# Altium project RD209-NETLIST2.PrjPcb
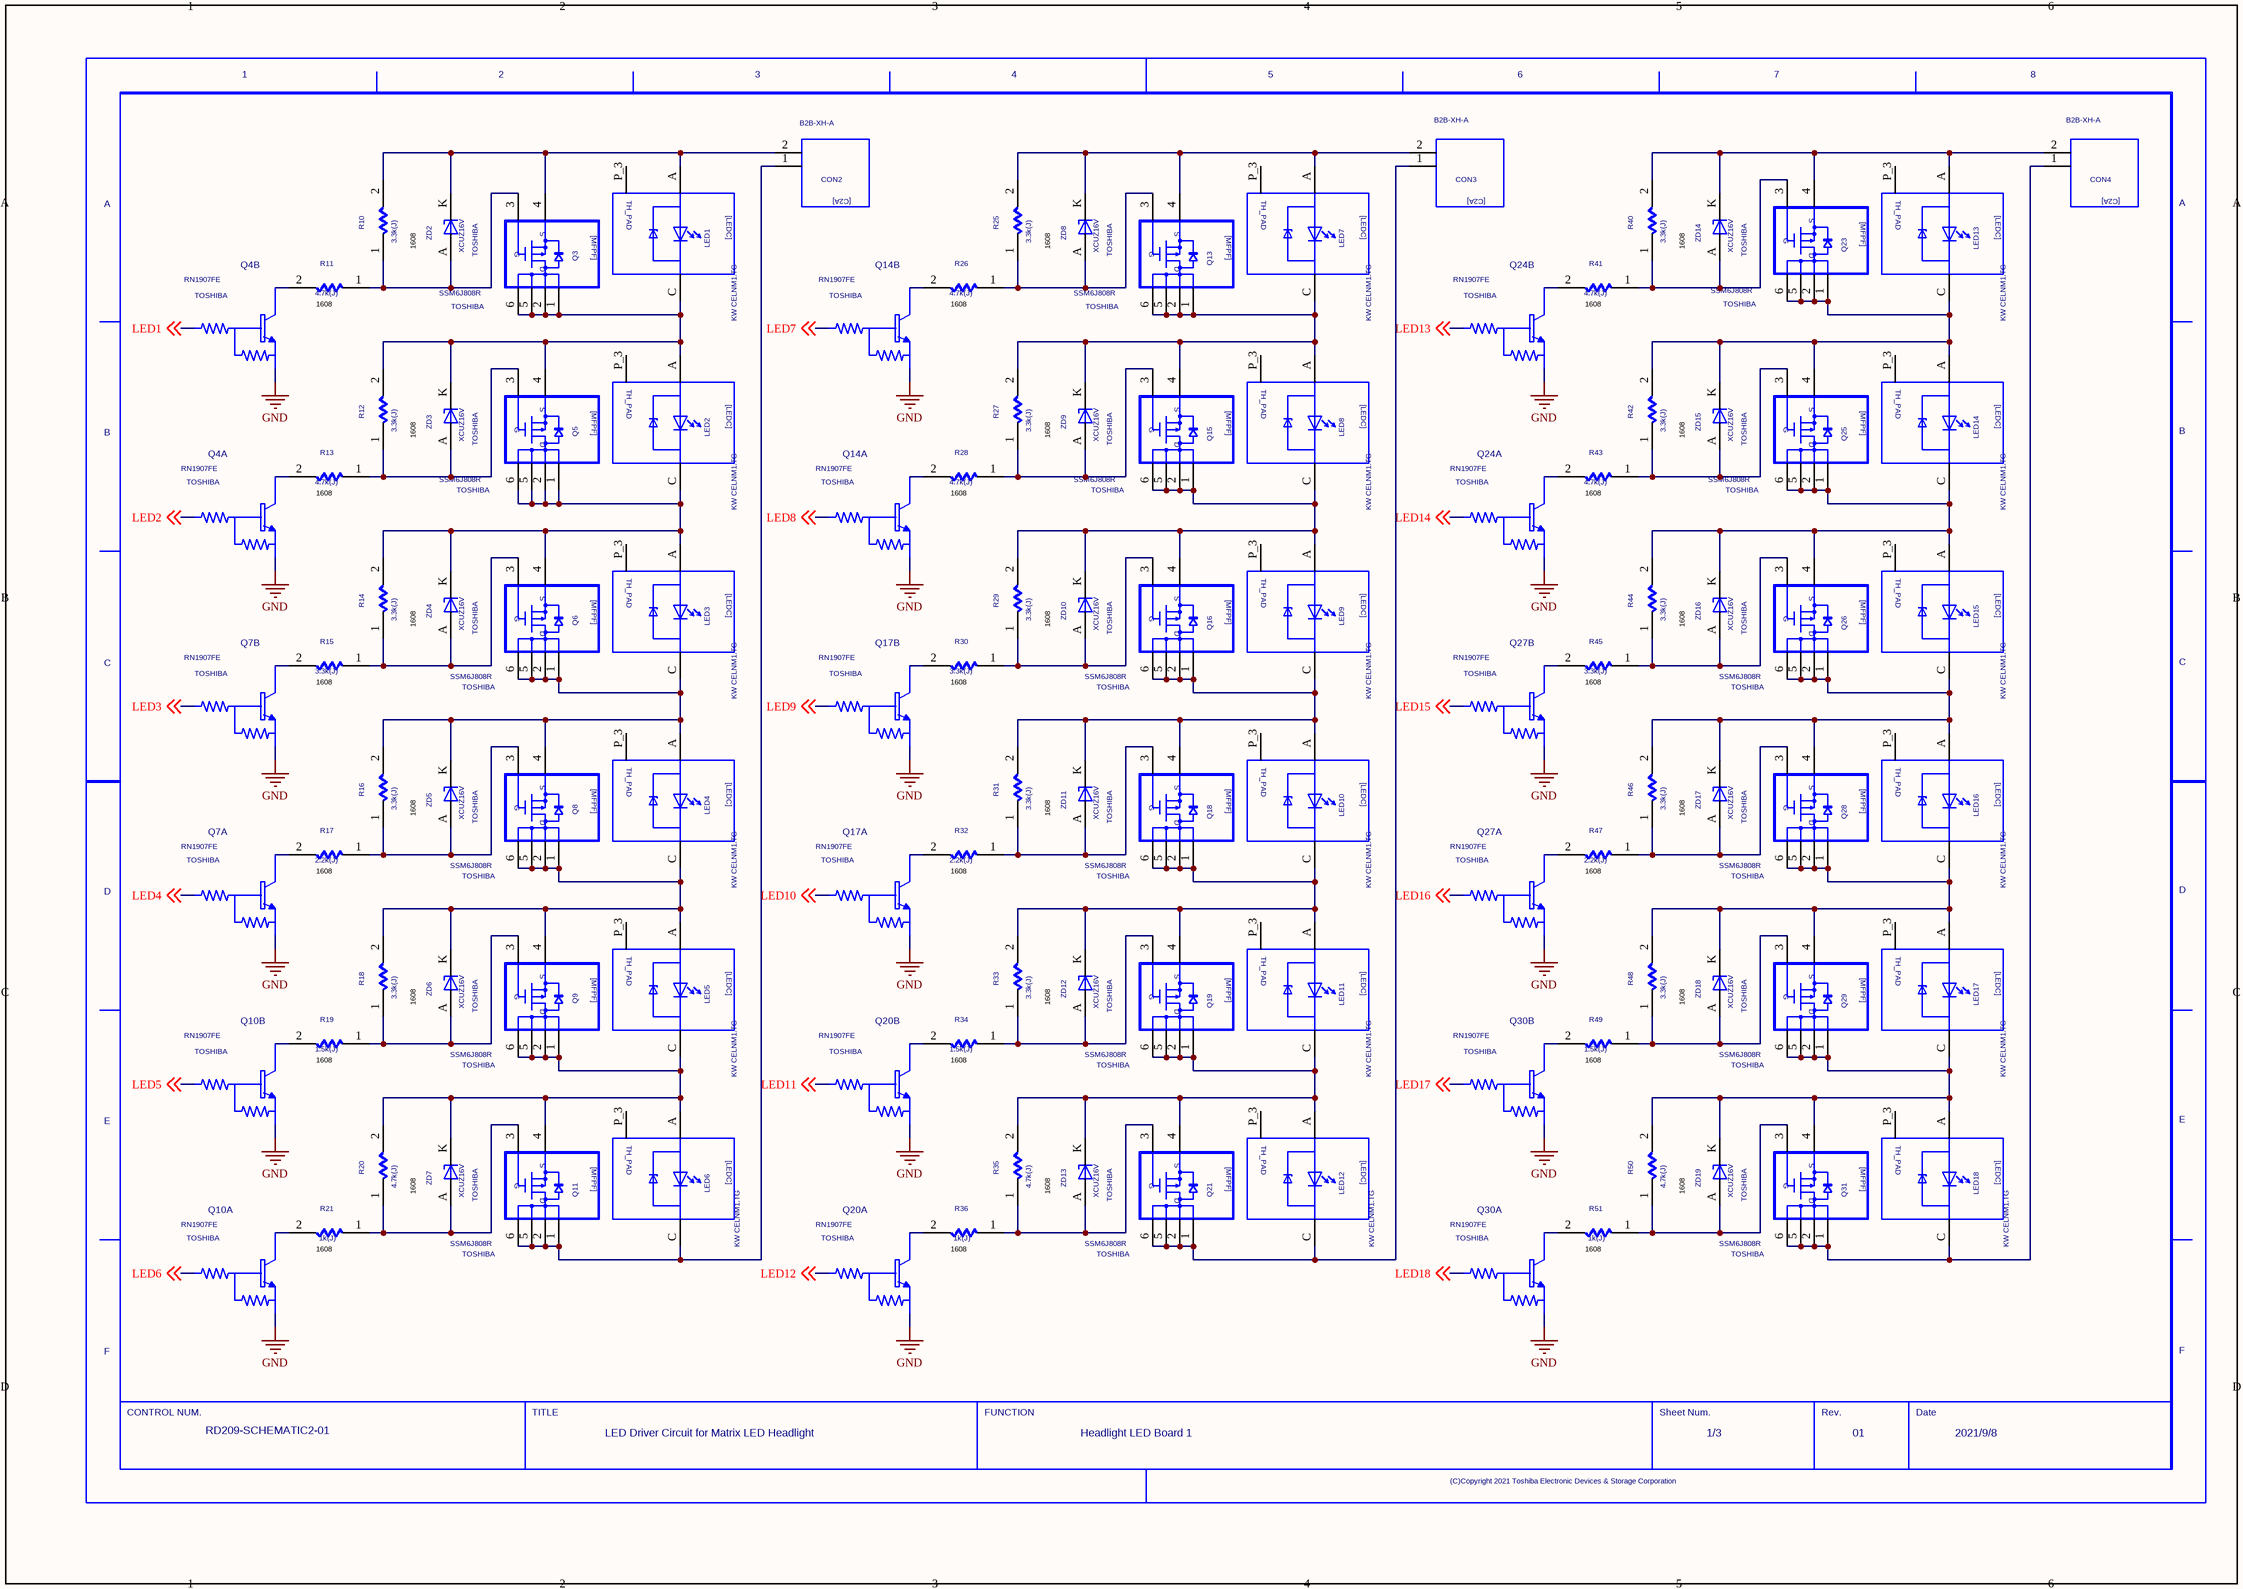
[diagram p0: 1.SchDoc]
3 sheets, 243 parts. Net scope: global (net labels, ports and power ports of the same name join across sheets).
Sheets:
  1.SchDoc
  2.SchDoc
  3.SchDoc

## Sheet 1.SchDoc
size 420 x 297 mm

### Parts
(Parts that share a designator on the sheet are numbered #1, #2 ... from top to bottom, then left to right.)
CON2  VAL3: B2B-XH-A  (hidden comment: C2A)
CON3  VAL3: B2B-XH-A  (hidden comment: C2A)
CON4  VAL3: B2B-XH-A  (hidden comment: C2A)
LED1  VAL3: KW CELNM1.TG  (hidden comment: LEDC)
LED2  VAL3: KW CELNM1.TG  (hidden comment: LEDC)
LED3  VAL3: KW CELNM1.TG  (hidden comment: LEDC)
LED4  VAL3: KW CELNM1.TG  (hidden comment: LEDC)
LED5  VAL3: KW CELNM1.TG  (hidden comment: LEDC)
LED6  VAL3: KW CELNM1.TG  (hidden comment: LEDC)
LED7  VAL3: KW CELNM1.TG  (hidden comment: LEDC)
LED8  VAL3: KW CELNM1.TG  (hidden comment: LEDC)
LED9  VAL3: KW CELNM1.TG  (hidden comment: LEDC)
LED10  VAL3: KW CELNM1.TG  (hidden comment: LEDC)
LED11  VAL3: KW CELNM1.TG  (hidden comment: LEDC)
LED12  VAL3: KW CELNM1.TG  (hidden comment: LEDC)
LED13  VAL3: KW CELNM1.TG  (hidden comment: LEDC)
LED14  VAL3: KW CELNM1.TG  (hidden comment: LEDC)
LED15  VAL3: KW CELNM1.TG  (hidden comment: LEDC)
LED16  VAL3: KW CELNM1.TG  (hidden comment: LEDC)
LED17  VAL3: KW CELNM1.TG  (hidden comment: LEDC)
LED18  VAL3: KW CELNM1.TG  (hidden comment: LEDC)
Q3  USERCOMPTEXT3: TOSHIBA  VAL3: SSM6J808R  (hidden comment: MFPF)
Q4  USERCOMPTEXT3: TOSHIBA  VAL3: RN1907FE  (hidden comment: RN1907FE_1)  (parts A,B of 2)
Q5  USERCOMPTEXT3: TOSHIBA  VAL3: SSM6J808R  (hidden comment: MFPF)
Q6  USERCOMPTEXT3: TOSHIBA  VAL3: SSM6J808R  (hidden comment: MFPF)
Q7  USERCOMPTEXT3: TOSHIBA  VAL3: RN1907FE  (hidden comment: RN1907FE_1)  (parts A,B of 2)
Q8  USERCOMPTEXT3: TOSHIBA  VAL3: SSM6J808R  (hidden comment: MFPF)
Q9  USERCOMPTEXT3: TOSHIBA  VAL3: SSM6J808R  (hidden comment: MFPF)
Q10  USERCOMPTEXT3: TOSHIBA  VAL3: RN1907FE  (hidden comment: RN1907FE_1)  (parts A,B of 2)
Q11  USERCOMPTEXT3: TOSHIBA  VAL3: SSM6J808R  (hidden comment: MFPF)
Q13  USERCOMPTEXT3: TOSHIBA  VAL3: SSM6J808R  (hidden comment: MFPF)
Q14  USERCOMPTEXT3: TOSHIBA  VAL3: RN1907FE  (hidden comment: RN1907FE_1)  (parts A,B of 2)
Q15  USERCOMPTEXT3: TOSHIBA  VAL3: SSM6J808R  (hidden comment: MFPF)
Q16  USERCOMPTEXT3: TOSHIBA  VAL3: SSM6J808R  (hidden comment: MFPF)
Q17  USERCOMPTEXT3: TOSHIBA  VAL3: RN1907FE  (hidden comment: RN1907FE_1)  (parts A,B of 2)
Q18  USERCOMPTEXT3: TOSHIBA  VAL3: SSM6J808R  (hidden comment: MFPF)
Q19  USERCOMPTEXT3: TOSHIBA  VAL3: SSM6J808R  (hidden comment: MFPF)
Q20  USERCOMPTEXT3: TOSHIBA  VAL3: RN1907FE  (hidden comment: RN1907FE_1)  (parts A,B of 2)
Q21  USERCOMPTEXT3: TOSHIBA  VAL3: SSM6J808R  (hidden comment: MFPF)
Q23  USERCOMPTEXT3: TOSHIBA  VAL3: SSM6J808R  (hidden comment: MFPF)
Q24  USERCOMPTEXT3: TOSHIBA  VAL3: RN1907FE  (hidden comment: RN1907FE_1)  (parts A,B of 2)
Q25  USERCOMPTEXT3: TOSHIBA  VAL3: SSM6J808R  (hidden comment: MFPF)
Q26  USERCOMPTEXT3: TOSHIBA  VAL3: SSM6J808R  (hidden comment: MFPF)
Q27  USERCOMPTEXT3: TOSHIBA  VAL3: RN1907FE  (hidden comment: RN1907FE_1)  (parts A,B of 2)
Q28  USERCOMPTEXT3: TOSHIBA  VAL3: SSM6J808R  (hidden comment: MFPF)
Q29  USERCOMPTEXT3: TOSHIBA  VAL3: SSM6J808R  (hidden comment: MFPF)
Q30  USERCOMPTEXT3: TOSHIBA  VAL3: RN1907FE  (hidden comment: RN1907FE_1)  (parts A,B of 2)
Q31  USERCOMPTEXT3: TOSHIBA  VAL3: SSM6J808R  (hidden comment: MFPF)
R10  VAL1: 3.3k(J)  (hidden comment: R)
R11  VAL1: 4.7k(J)  (hidden comment: R)
R12  VAL1: 3.3k(J)  (hidden comment: R)
R13  VAL1: 4.7k(J)  (hidden comment: R)
R14  VAL1: 3.3k(J)  (hidden comment: R)
R15  VAL1: 3.3k(J)  (hidden comment: R)
R16  VAL1: 3.3k(J)  (hidden comment: R)
R17  VAL1: 2.2k(J)  (hidden comment: R)
R18  VAL1: 3.3k(J)  (hidden comment: R)
R19  VAL1: 1.5k(J)  (hidden comment: R)
R20  VAL1: 4.7k(J)  (hidden comment: R)
R21  VAL1: 1k(J)  (hidden comment: R)
R25  VAL1: 3.3k(J)  (hidden comment: R)
R26  VAL1: 4.7k(J)  (hidden comment: R)
R27  VAL1: 3.3k(J)  (hidden comment: R)
R28  VAL1: 4.7k(J)  (hidden comment: R)
R29  VAL1: 3.3k(J)  (hidden comment: R)
R30  VAL1: 3.3k(J)  (hidden comment: R)
R31  VAL1: 3.3k(J)  (hidden comment: R)
R32  VAL1: 2.2k(J)  (hidden comment: R)
R33  VAL1: 3.3k(J)  (hidden comment: R)
R34  VAL1: 1.5k(J)  (hidden comment: R)
R35  VAL1: 4.7k(J)  (hidden comment: R)
R36  VAL1: 1k(J)  (hidden comment: R)
R40  VAL1: 3.3k(J)  (hidden comment: R)
R41  VAL1: 4.7k(J)  (hidden comment: R)
R42  VAL1: 3.3k(J)  (hidden comment: R)
R43  VAL1: 4.7k(J)  (hidden comment: R)
R44  VAL1: 3.3k(J)  (hidden comment: R)
R45  VAL1: 3.3k(J)  (hidden comment: R)
R46  VAL1: 3.3k(J)  (hidden comment: R)
R47  VAL1: 2.2k(J)  (hidden comment: R)
R48  VAL1: 3.3k(J)  (hidden comment: R)
R49  VAL1: 1.5k(J)  (hidden comment: R)
R50  VAL1: 4.7k(J)  (hidden comment: R)
R51  VAL1: 1k(J)  (hidden comment: R)
U?#1  DATE: 2021/9/8  REVISION: 01  SHEETNUMBER: 1/3  FUNCTION: Headlight LED Board 1  TITLE: LED Driver Circuit for / Matrix LED Headlight  DRAWINGNUMBER: RD209-SCHEMATIC2-01  (hidden comment: WAKU_DEF100)
ZD2  USERCOMPTEXT3: TOSHIBA  VAL3: XCUZ16V  (hidden comment: ZD)
ZD3  USERCOMPTEXT3: TOSHIBA  VAL3: XCUZ16V  (hidden comment: ZD)
ZD4  USERCOMPTEXT3: TOSHIBA  VAL3: XCUZ16V  (hidden comment: ZD)
ZD5  USERCOMPTEXT3: TOSHIBA  VAL3: XCUZ16V  (hidden comment: ZD)
ZD6  USERCOMPTEXT3: TOSHIBA  VAL3: XCUZ16V  (hidden comment: ZD)
ZD7  USERCOMPTEXT3: TOSHIBA  VAL3: XCUZ16V  (hidden comment: ZD)
ZD8  USERCOMPTEXT3: TOSHIBA  VAL3: XCUZ16V  (hidden comment: ZD)
ZD9  USERCOMPTEXT3: TOSHIBA  VAL3: XCUZ16V  (hidden comment: ZD)
ZD10  USERCOMPTEXT3: TOSHIBA  VAL3: XCUZ16V  (hidden comment: ZD)
ZD11  USERCOMPTEXT3: TOSHIBA  VAL3: XCUZ16V  (hidden comment: ZD)
ZD12  USERCOMPTEXT3: TOSHIBA  VAL3: XCUZ16V  (hidden comment: ZD)
ZD13  USERCOMPTEXT3: TOSHIBA  VAL3: XCUZ16V  (hidden comment: ZD)
ZD14  USERCOMPTEXT3: TOSHIBA  VAL3: XCUZ16V  (hidden comment: ZD)
ZD15  USERCOMPTEXT3: TOSHIBA  VAL3: XCUZ16V  (hidden comment: ZD)
ZD16  USERCOMPTEXT3: TOSHIBA  VAL3: XCUZ16V  (hidden comment: ZD)
ZD17  USERCOMPTEXT3: TOSHIBA  VAL3: XCUZ16V  (hidden comment: ZD)
ZD18  USERCOMPTEXT3: TOSHIBA  VAL3: XCUZ16V  (hidden comment: ZD)
ZD19  USERCOMPTEXT3: TOSHIBA  VAL3: XCUZ16V  (hidden comment: ZD)

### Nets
GND: Q4.1 Q4.4 Q7.1 Q7.4 Q10.1 Q10.4 Q14.1 Q14.4 Q17.1 Q17.4 Q20.1 Q20.4 Q24.1 Q24.4 Q27.1 Q27.4 Q30.1 Q30.4  [also labelled SIG12, SIG18, SIG21, SIG26, SIG30, SIG34, SIG35, SIG40, SIG45, SIG51, SIG54, SIG59, SIG60, SIG66, SIG72, SIG74, SIG8]  [project net SIG101]
LED2: Q4.2 ; off-sheet LED2
LED3: Q7.5 ; off-sheet LED3
LED4: Q7.2 ; off-sheet LED4
LED5: Q10.5 ; off-sheet LED5
LED6: Q10.2 ; off-sheet LED6
LED7: Q14.5 ; off-sheet LED7
LED8: Q14.2 ; off-sheet LED8
LED9: Q17.5 ; off-sheet LED9
LED10: Q17.2 ; off-sheet LED10
LED11: Q20.5 ; off-sheet LED11
LED12: Q20.2 ; off-sheet LED12
LED13: Q24.5 ; off-sheet LED13
LED14: Q24.2 ; off-sheet LED14
LED15: Q27.5 ; off-sheet LED15
LED16: Q27.2 ; off-sheet LED16
LED17: Q30.5 ; off-sheet LED17
LED18: Q30.2 ; off-sheet LED18
LED+1: CON2.2 LED1.A Q3.4 R10.2 ZD2.K(C)
LED+2: CON3.2 LED7.A Q13.4 R25.2 ZD8.K(C)
LED+3: CON4.2 LED13.A Q23.4 R40.2 ZD14.K(C)
LED-1: CON2.1 LED6.C Q11.1 Q11.2 Q11.5 Q11.6
LED-2: CON3.1 LED12.C Q21.1 Q21.2 Q21.5 Q21.6
SIG1: Q4.5 ; off-sheet LED1  [also labelled LED1]
SIG2: Q4.3 R11.2
SIG3: Q3.3 R10.1 R11.1 ZD2.A
SIG6: Q5.3 R12.1 R13.1 ZD3.A
SIG7: Q4.6 R13.2
SIG10: Q7.6 R17.2
SIG11: Q8.3 R16.1 R17.1 ZD5.A
SIG15: LED3.C LED4.A Q6.1 Q6.2 Q6.5 Q6.6 Q8.4 R16.2 ZD5.K(C)
SIG16: Q6.3 R14.1 R15.1 ZD4.A
SIG17: Q7.3 R15.2
SIG19: Q10.6 R21.2
SIG20: Q11.3 R20.1 R21.1 ZD7.A
SIG23: LED5.C LED6.A Q9.1 Q9.2 Q9.5 Q9.6 Q11.4 R20.2 ZD7.K(C)
SIG24: Q9.3 R18.1 R19.1 ZD6.A
SIG25: Q10.3 R19.2
SIG28: LED2.C LED3.A Q5.1 Q5.2 Q5.5 Q5.6 Q6.4 R14.2 ZD4.K(C)
SIG29: Q20.3 R34.2
SIG32: Q13.3 R25.1 R26.1 ZD8.A
SIG33: Q14.3 R26.2
SIG36: Q21.3 R35.1 R36.1 ZD13.A
SIG37: Q20.6 R36.2
SIG38: Q17.3 R30.2
SIG39: LED9.C LED10.A Q16.1 Q16.2 Q16.5 Q16.6 Q18.4 R31.2 ZD11.K(C)
SIG42: LED8.C LED9.A Q15.1 Q15.2 Q15.5 Q15.6 Q16.4 R29.2 ZD10.K(C)
SIG43: LED10.C LED11.A Q18.1 Q18.2 Q18.5 Q18.6 Q19.4 R33.2 ZD12.K(C)
SIG44: LED7.C LED8.A Q13.1 Q13.2 Q13.5 Q13.6 Q15.4 R27.2 ZD9.K(C)
SIG46: Q17.6 R32.2
SIG47: LED11.C LED12.A Q19.1 Q19.2 Q19.5 Q19.6 Q21.4 R35.2 ZD13.K(C)
SIG48: Q16.3 R29.1 R30.1 ZD10.A
SIG49: Q18.3 R31.1 R32.1 ZD11.A
SIG50: Q15.3 R27.1 R28.1 ZD9.A
SIG52: Q14.6 R28.2
SIG55: Q27.3 R45.2
SIG57: LED15.C LED16.A Q26.1 Q26.2 Q26.5 Q26.6 Q28.4 R46.2 ZD17.K(C)
SIG58: LED14.C LED15.A Q25.1 Q25.2 Q25.5 Q25.6 Q26.4 R44.2 ZD16.K(C)
SIG61: Q29.3 R48.1 R49.1 ZD18.A
SIG62: Q24.3 R41.2
SIG63: Q31.3 R50.1 R51.1 ZD19.A
SIG64: Q23.3 R40.1 R41.1 ZD14.A
SIG65: Q30.6 R51.2
SIG67: Q30.3 R49.2
SIG69: Q24.6 R43.2
SIG71: Q28.3 R46.1 R47.1 ZD17.A
SIG73: LED13.C LED14.A Q23.1 Q23.2 Q23.5 Q23.6 Q25.4 R42.2 ZD15.K(C)
SIG75: Q26.3 R44.1 R45.1 ZD16.A
SIG76: LED16.C LED17.A Q28.1 Q28.2 Q28.5 Q28.6 Q29.4 R48.2 ZD18.K(C)
SIG77: LED17.C LED18.A Q29.1 Q29.2 Q29.5 Q29.6 Q31.4 R50.2 ZD19.K(C)
SIG78: Q27.6 R47.2
SIG214: LED1.C LED2.A Q3.1 Q3.2 Q3.5 Q3.6 Q5.4 R12.2 ZD3.K(C)
SIG215: LED4.C LED5.A Q8.1 Q8.2 Q8.5 Q8.6 Q9.4 R18.2 ZD6.K(C)
SIG216: Q19.3 R33.1 R34.1 ZD12.A
SIG217: Q25.3 R42.1 R43.1 ZD15.A
SIG218: CON4.1 LED18.C Q31.1 Q31.2 Q31.5 Q31.6

Not connected (* = marked no-connect by the designer): LED1 P_3(NC); LED2 P_3(NC); LED3 P_3(NC); LED4 P_3(NC); LED5 P_3(NC); LED6 P_3(NC); LED7 P_3(NC); LED8 P_3(NC); LED9 P_3(NC); LED10 P_3(NC); LED11 P_3(NC); LED12 P_3(NC); LED13 P_3(NC); LED14 P_3(NC); LED15 P_3(NC); LED16 P_3(NC); LED17 P_3(NC); LED18 P_3(NC)

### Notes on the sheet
- 1608
- (near R11) 1608
- (near R26) 1608
- (near R41) 1608
- (near R13) 1608
- (near R28) 1608
- (near R43) 1608
- (near R15) 1608
- (near R30) 1608
- (near R45) 1608
- (near R17) 1608
- (near R32) 1608
- (near R47) 1608
- (near R19) 1608
- (near R34) 1608
- (near R49) 1608
- (near R21) 1608
- (near R36) 1608
- (near R51) 1608

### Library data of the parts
CON2-CON4 = C2A: SAVEAREA0: -4611,-206,24632,18258; SAVECOUNT: 25; TIME: 13:28:28; UPDATEUSER: tomizawa-y; UPDATETIME: 12:08:31; OriginalSymbolOrigin: (2540,15240)
LED1-LED18 = LEDC: SAVEAREA0: -10936,-329,35896,28705; TIME: 14:49:55; UPDATEUSER: fukuda-y; UPDATETIME: 15:53:51; SAVECOUNT: 15; OriginalSymbolOrigin: (5080,25400); COMPONENTNAME: LED; CDBNAME: KW
Q3 Q5 Q6 Q8 Q9 Q11 Q13 Q15 Q16 Q18 Q19 Q21 Q23 Q25 Q26 Q28 Q29 Q31 = MFPF: SAVECOUNT: 11; SAVEAREA0: -6011,0,28984,22860; OriginalSymbolOrigin: (5080,20320); COMPONENTNAME: TSOP6F
Q4 Q7 Q10 Q14 Q17 Q20 Q24 Q27 Q30 = RN1907FE_1: COMP: ES6; TIME: 08:46:53; UPDATEUSER: t5459927; UPDATETIME: 14:30:50; SAVECOUNT: 6; SAVEAREA0: -3836,-13019,18528,3377; OriginalSymbolOrigin: (0,5080); CaptureCellPackProp: RN1907FE_1A
R10 R19 R25 R34 R40 R49 = R: OriginalSymbolOrigin: (5080,5080); COMPONENTNAME: R0603_1; VAL2: 100mW
R11 R18 R26 R33 R41 R48 = R: OriginalSymbolOrigin: (5080,5080); COMPONENTNAME: R0603_2; VAL2: 100mW
R12 R27 R42 = R: OriginalSymbolOrigin: (5080,5080); VAL2: 100mW; COMPONENTNAME: R0603_3
R13 R15 R28 R30 R43 R45 = R: OriginalSymbolOrigin: (5080,5080); COMPONENTNAME: R0603_4; VAL2: 100mW
R14 R17 R29 R32 R44 R47 = R: OriginalSymbolOrigin: (5080,5080); COMPONENTNAME: R0603_5; VAL2: 100mW
R16 R31 R46 = R: OriginalSymbolOrigin: (5080,5080); VAL2: 100mW; COMPONENTNAME: R0603_6
R20 R35 R50 = R: OriginalSymbolOrigin: (5080,5080); VAL2: 100mW; COMPONENTNAME: R0603_7
R21 R36 R51 = R: OriginalSymbolOrigin: (5080,5080); COMPONENTNAME: R0603_8; VAL2: 100mW
U?#1 = WAKU_DEF100: PLOTTIME: HH:MM; SAVEAREA0: 148187,-66180,486823,89919; TIME: 14:30:25; UPDATEUSER: t5459927; UPDATETIME: 14:28:22; SAVECOUNT: 6; OriginalSymbolOrigin: (10160,284480)
ZD2-ZD19 = ZD: SAVEAREA0: -4630,-153,17114,13055; TIME: 14:49:55; UPDATEUSER: fukuda-y; UPDATETIME: 08:18:42; SAVECOUNT: 6; OriginalSymbolOrigin: (5080,5080); COMPONENTNAME: USC

## Sheet 2.SchDoc
size 420 x 297 mm
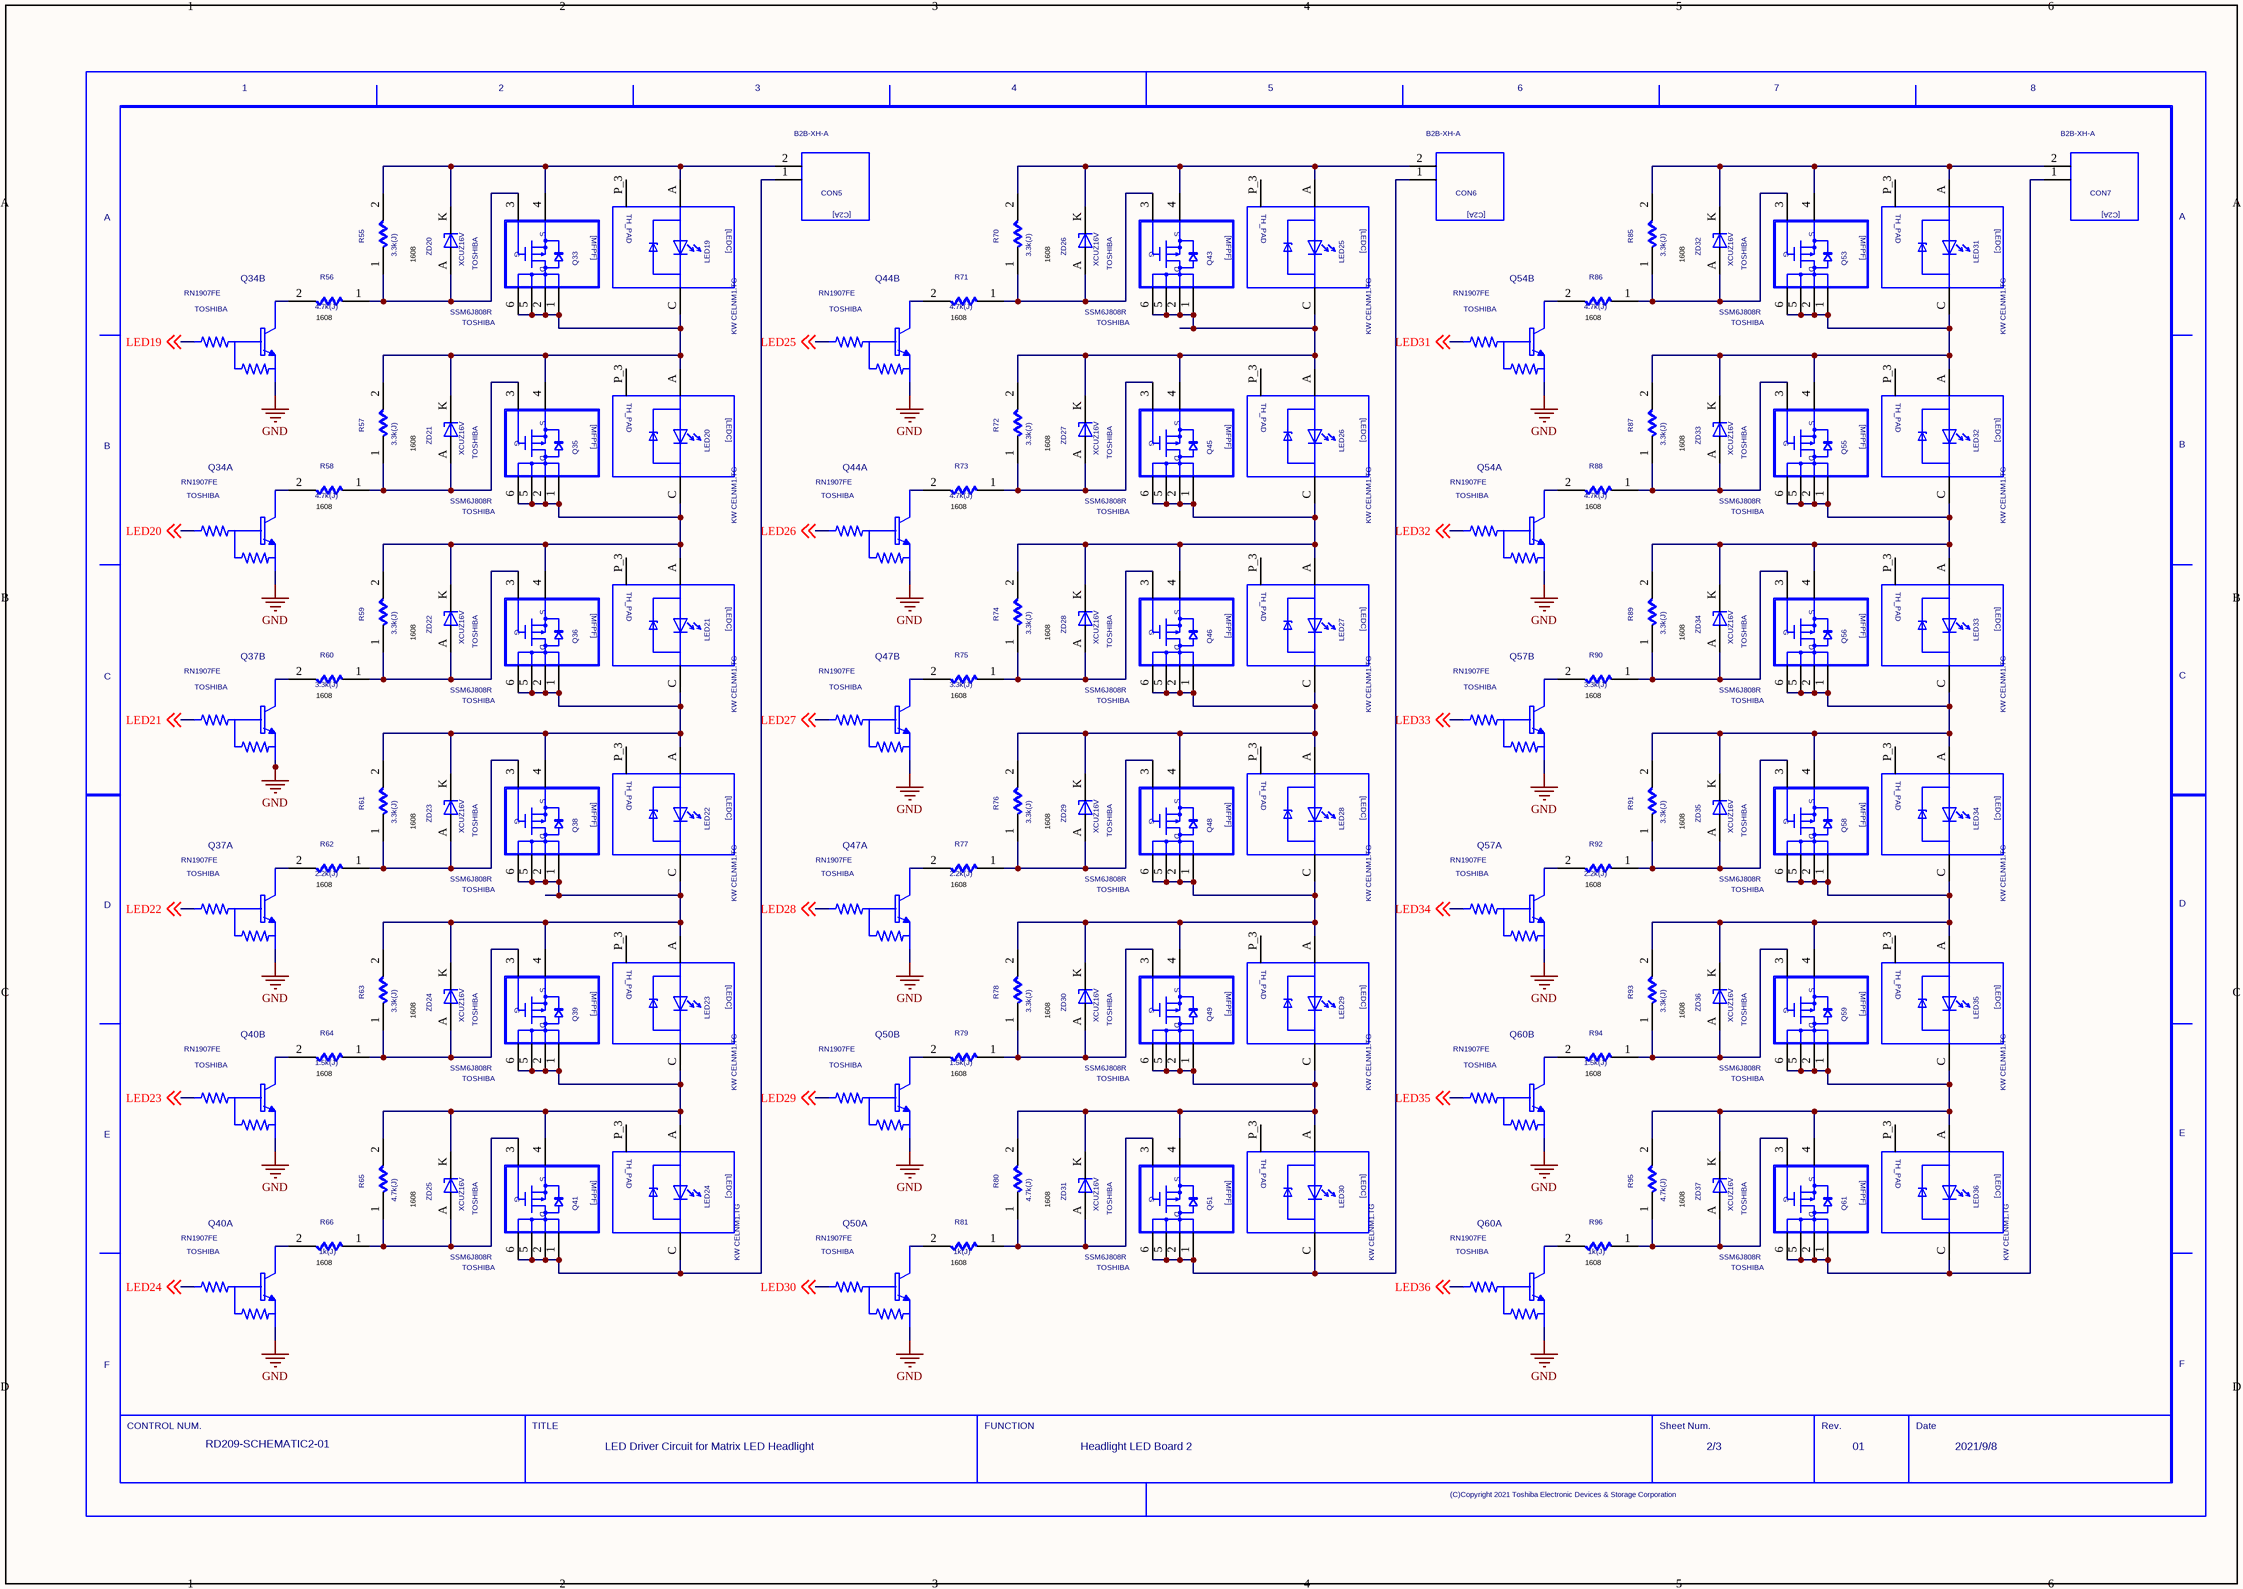
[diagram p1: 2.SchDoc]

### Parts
(Parts that share a designator on the sheet are numbered #1, #2 ... from top to bottom, then left to right.)
CON5  VAL3: B2B-XH-A  (hidden comment: C2A)
CON6  VAL3: B2B-XH-A  (hidden comment: C2A)
CON7  VAL3: B2B-XH-A  (hidden comment: C2A)
LED19  VAL3: KW CELNM1.TG  (hidden comment: LEDC)
LED20  VAL3: KW CELNM1.TG  (hidden comment: LEDC)
LED21  VAL3: KW CELNM1.TG  (hidden comment: LEDC)
LED22  VAL3: KW CELNM1.TG  (hidden comment: LEDC)
LED23  VAL3: KW CELNM1.TG  (hidden comment: LEDC)
LED24  VAL3: KW CELNM1.TG  (hidden comment: LEDC)
LED25  VAL3: KW CELNM1.TG  (hidden comment: LEDC)
LED26  VAL3: KW CELNM1.TG  (hidden comment: LEDC)
LED27  VAL3: KW CELNM1.TG  (hidden comment: LEDC)
LED28  VAL3: KW CELNM1.TG  (hidden comment: LEDC)
LED29  VAL3: KW CELNM1.TG  (hidden comment: LEDC)
LED30  VAL3: KW CELNM1.TG  (hidden comment: LEDC)
LED31  VAL3: KW CELNM1.TG  (hidden comment: LEDC)
LED32  VAL3: KW CELNM1.TG  (hidden comment: LEDC)
LED33  VAL3: KW CELNM1.TG  (hidden comment: LEDC)
LED34  VAL3: KW CELNM1.TG  (hidden comment: LEDC)
LED35  VAL3: KW CELNM1.TG  (hidden comment: LEDC)
LED36  VAL3: KW CELNM1.TG  (hidden comment: LEDC)
Q33  USERCOMPTEXT3: TOSHIBA  VAL3: SSM6J808R  (hidden comment: MFPF)
Q34  USERCOMPTEXT3: TOSHIBA  VAL3: RN1907FE  (hidden comment: RN1907FE_1)  (parts A,B of 2)
Q35  USERCOMPTEXT3: TOSHIBA  VAL3: SSM6J808R  (hidden comment: MFPF)
Q36  USERCOMPTEXT3: TOSHIBA  VAL3: SSM6J808R  (hidden comment: MFPF)
Q37  USERCOMPTEXT3: TOSHIBA  VAL3: RN1907FE  (hidden comment: RN1907FE_1)  (parts A,B of 2)
Q38  USERCOMPTEXT3: TOSHIBA  VAL3: SSM6J808R  (hidden comment: MFPF)
Q39  USERCOMPTEXT3: TOSHIBA  VAL3: SSM6J808R  (hidden comment: MFPF)
Q40  USERCOMPTEXT3: TOSHIBA  VAL3: RN1907FE  (hidden comment: RN1907FE_1)  (parts A,B of 2)
Q41  USERCOMPTEXT3: TOSHIBA  VAL3: SSM6J808R  (hidden comment: MFPF)
Q43  USERCOMPTEXT3: TOSHIBA  VAL3: SSM6J808R  (hidden comment: MFPF)
Q44  USERCOMPTEXT3: TOSHIBA  VAL3: RN1907FE  (hidden comment: RN1907FE_1)  (parts A,B of 2)
Q45  USERCOMPTEXT3: TOSHIBA  VAL3: SSM6J808R  (hidden comment: MFPF)
Q46  USERCOMPTEXT3: TOSHIBA  VAL3: SSM6J808R  (hidden comment: MFPF)
Q47  USERCOMPTEXT3: TOSHIBA  VAL3: RN1907FE  (hidden comment: RN1907FE_1)  (parts A,B of 2)
Q48  USERCOMPTEXT3: TOSHIBA  VAL3: SSM6J808R  (hidden comment: MFPF)
Q49  USERCOMPTEXT3: TOSHIBA  VAL3: SSM6J808R  (hidden comment: MFPF)
Q50  USERCOMPTEXT3: TOSHIBA  VAL3: RN1907FE  (hidden comment: RN1907FE_1)  (parts A,B of 2)
Q51  USERCOMPTEXT3: TOSHIBA  VAL3: SSM6J808R  (hidden comment: MFPF)
Q53  USERCOMPTEXT3: TOSHIBA  VAL3: SSM6J808R  (hidden comment: MFPF)
Q54  USERCOMPTEXT3: TOSHIBA  VAL3: RN1907FE  (hidden comment: RN1907FE_1)  (parts A,B of 2)
Q55  USERCOMPTEXT3: TOSHIBA  VAL3: SSM6J808R  (hidden comment: MFPF)
Q56  USERCOMPTEXT3: TOSHIBA  VAL3: SSM6J808R  (hidden comment: MFPF)
Q57  USERCOMPTEXT3: TOSHIBA  VAL3: RN1907FE  (hidden comment: RN1907FE_1)  (parts A,B of 2)
Q58  USERCOMPTEXT3: TOSHIBA  VAL3: SSM6J808R  (hidden comment: MFPF)
Q59  USERCOMPTEXT3: TOSHIBA  VAL3: SSM6J808R  (hidden comment: MFPF)
Q60  USERCOMPTEXT3: TOSHIBA  VAL3: RN1907FE  (hidden comment: RN1907FE_1)  (parts A,B of 2)
Q61  USERCOMPTEXT3: TOSHIBA  VAL3: SSM6J808R  (hidden comment: MFPF)
R55  VAL1: 3.3k(J)  (hidden comment: R)
R56  VAL1: 4.7k(J)  (hidden comment: R)
R57  VAL1: 3.3k(J)  (hidden comment: R)
R58  VAL1: 4.7k(J)  (hidden comment: R)
R59  VAL1: 3.3k(J)  (hidden comment: R)
R60  VAL1: 3.3k(J)  (hidden comment: R)
R61  VAL1: 3.3k(J)  (hidden comment: R)
R62  VAL1: 2.2k(J)  (hidden comment: R)
R63  VAL1: 3.3k(J)  (hidden comment: R)
R64  VAL1: 1.5k(J)  (hidden comment: R)
R65  VAL1: 4.7k(J)  (hidden comment: R)
R66  VAL1: 1k(J)  (hidden comment: R)
R70  VAL1: 3.3k(J)  (hidden comment: R)
R71  VAL1: 4.7k(J)  (hidden comment: R)
R72  VAL1: 3.3k(J)  (hidden comment: R)
R73  VAL1: 4.7k(J)  (hidden comment: R)
R74  VAL1: 3.3k(J)  (hidden comment: R)
R75  VAL1: 3.3k(J)  (hidden comment: R)
R76  VAL1: 3.3k(J)  (hidden comment: R)
R77  VAL1: 2.2k(J)  (hidden comment: R)
R78  VAL1: 3.3k(J)  (hidden comment: R)
R79  VAL1: 1.5k(J)  (hidden comment: R)
R80  VAL1: 4.7k(J)  (hidden comment: R)
R81  VAL1: 1k(J)  (hidden comment: R)
R85  VAL1: 3.3k(J)  (hidden comment: R)
R86  VAL1: 4.7k(J)  (hidden comment: R)
R87  VAL1: 3.3k(J)  (hidden comment: R)
R88  VAL1: 4.7k(J)  (hidden comment: R)
R89  VAL1: 3.3k(J)  (hidden comment: R)
R90  VAL1: 3.3k(J)  (hidden comment: R)
R91  VAL1: 3.3k(J)  (hidden comment: R)
R92  VAL1: 2.2k(J)  (hidden comment: R)
R93  VAL1: 3.3k(J)  (hidden comment: R)
R94  VAL1: 1.5k(J)  (hidden comment: R)
R95  VAL1: 4.7k(J)  (hidden comment: R)
R96  VAL1: 1k(J)  (hidden comment: R)
U?#2  DATE: 2021/9/8  REVISION: 01  SHEETNUMBER: 2/3  FUNCTION: Headlight LED Board 2  TITLE: LED Driver Circuit for / Matrix LED Headlight  DRAWINGNUMBER: RD209-SCHEMATIC2-01  (hidden comment: WAKU_DEF100)
ZD20  USERCOMPTEXT3: TOSHIBA  VAL3: XCUZ16V  (hidden comment: ZD)
ZD21  USERCOMPTEXT3: TOSHIBA  VAL3: XCUZ16V  (hidden comment: ZD)
ZD22  USERCOMPTEXT3: TOSHIBA  VAL3: XCUZ16V  (hidden comment: ZD)
ZD23  USERCOMPTEXT3: TOSHIBA  VAL3: XCUZ16V  (hidden comment: ZD)
ZD24  USERCOMPTEXT3: TOSHIBA  VAL3: XCUZ16V  (hidden comment: ZD)
ZD25  USERCOMPTEXT3: TOSHIBA  VAL3: XCUZ16V  (hidden comment: ZD)
ZD26  USERCOMPTEXT3: TOSHIBA  VAL3: XCUZ16V  (hidden comment: ZD)
ZD27  USERCOMPTEXT3: TOSHIBA  VAL3: XCUZ16V  (hidden comment: ZD)
ZD28  USERCOMPTEXT3: TOSHIBA  VAL3: XCUZ16V  (hidden comment: ZD)
ZD29  USERCOMPTEXT3: TOSHIBA  VAL3: XCUZ16V  (hidden comment: ZD)
ZD30  USERCOMPTEXT3: TOSHIBA  VAL3: XCUZ16V  (hidden comment: ZD)
ZD31  USERCOMPTEXT3: TOSHIBA  VAL3: XCUZ16V  (hidden comment: ZD)
ZD32  USERCOMPTEXT3: TOSHIBA  VAL3: XCUZ16V  (hidden comment: ZD)
ZD33  USERCOMPTEXT3: TOSHIBA  VAL3: XCUZ16V  (hidden comment: ZD)
ZD34  USERCOMPTEXT3: TOSHIBA  VAL3: XCUZ16V  (hidden comment: ZD)
ZD35  USERCOMPTEXT3: TOSHIBA  VAL3: XCUZ16V  (hidden comment: ZD)
ZD36  USERCOMPTEXT3: TOSHIBA  VAL3: XCUZ16V  (hidden comment: ZD)
ZD37  USERCOMPTEXT3: TOSHIBA  VAL3: XCUZ16V  (hidden comment: ZD)

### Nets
SIG101: Q34.1 Q34.4 Q37.1 Q37.4 Q40.1 Q40.4 Q44.1 Q44.4 Q47.1 Q47.4 Q50.1 Q50.4 Q54.1 Q54.4 Q57.1 Q57.4 Q60.1 Q60.4  [also labelled GND, SIG105, SIG113, SIG116, SIG117, SIG134, SIG136, SIG143, SIG147, SIG151, SIG154, SIG158, SIG159, SIG166, SIG171, SIG84, SIG88, SIG90]
LED19: Q34.5 ; off-sheet LED19
LED20: Q34.2 ; off-sheet LED20
LED21: Q37.5 ; off-sheet LED21
LED22: Q37.2 ; off-sheet LED22
LED23: Q40.5 ; off-sheet LED23
LED24: Q40.2 ; off-sheet LED24
LED25: Q44.5 ; off-sheet LED25
LED26: Q44.2 ; off-sheet LED26
LED27: Q47.5 ; off-sheet LED27
LED28: Q47.2 ; off-sheet LED28
LED29: Q50.5 ; off-sheet LED29
LED30: Q50.2 ; off-sheet LED30
LED31: Q54.5 ; off-sheet LED31
LED32: Q54.2 ; off-sheet LED32
LED33: Q57.5 ; off-sheet LED33
LED34: Q57.2 ; off-sheet LED34
LED35: Q60.5 ; off-sheet LED35
LED36: Q60.2 ; off-sheet LED36
LED+4: CON5.2 LED19.A Q33.4 R55.2 ZD20.K(C)
LED+5: CON6.2 LED25.A Q43.4 R70.2 ZD26.K(C)
LED+6: CON7.2 LED31.A Q53.4 R85.2 ZD32.K(C)
LED-4: CON5.1 LED24.C Q41.1 Q41.2 Q41.5 Q41.6
SIG79: LED26.C LED27.A Q45.1 Q45.2 Q45.5 Q45.6 Q46.4 R74.2 ZD28.K(C)
SIG80: LED25.C LED26.A Q43.1 Q43.2 Q43.5 Q43.6 Q45.4 R72.2 ZD27.K(C)
SIG81: LED28.C LED29.A Q48.1 Q48.2 Q48.5 Q48.6 Q49.4 R78.2 ZD30.K(C)
SIG86: LED27.C LED28.A Q46.1 Q46.2 Q46.5 Q46.6 Q48.4 R76.2 ZD29.K(C)
SIG87: Q50.6 R81.2
SIG92: Q47.3 R75.2
SIG96: LED21.C LED22.A Q36.1 Q36.2 Q36.5 Q36.6 Q38.4 R61.2 ZD23.K(C)
SIG97: LED35.C LED36.A Q59.1 Q59.2 Q59.5 Q59.6 Q61.4 R95.2 ZD37.K(C)
SIG98: Q50.3 R79.2
SIG99: Q57.6 R92.2
SIG100: Q44.3 R71.2
SIG102: Q43.3 R70.1 R71.1 ZD26.A
SIG103: Q58.3 R91.1 R92.1 ZD35.A
SIG104: LED34.C LED35.A Q58.1 Q58.2 Q58.5 Q58.6 Q59.4 R93.2 ZD36.K(C)
SIG110: LED23.C LED24.A Q39.1 Q39.2 Q39.5 Q39.6 Q41.4 R65.2 ZD25.K(C)
SIG112: LED19.C LED20.A Q33.1 Q33.2 Q33.5 Q33.6 Q35.4 R57.2 ZD21.K(C)
SIG114: LED20.C LED21.A Q35.1 Q35.2 Q35.5 Q35.6 Q36.4 R59.2 ZD22.K(C)
SIG115: Q54.6 R88.2
SIG121: Q59.3 R93.1 R94.1 ZD36.A
SIG124: Q61.3 R95.1 R96.1 ZD37.A
SIG128: Q40.3 R64.2
SIG129: Q60.3 R94.2
SIG130: Q60.6 R96.2
SIG131: Q54.3 R86.2
SIG133: Q40.6 R66.2
SIG135: Q53.3 R85.1 R86.1 ZD32.A
SIG137: Q37.3 R60.2
SIG138: Q39.3 R63.1 R64.1 ZD24.A
SIG141: Q35.3 R57.1 R58.1 ZD21.A
SIG142: Q37.6 R62.2
SIG144: LED22.C LED23.A Q38.1 Q38.2 Q38.5 Q38.6 Q39.4 R63.2 ZD24.K(C)
SIG145: Q38.3 R61.1 R62.1 ZD23.A
SIG146: LED33.C LED34.A Q56.1 Q56.2 Q56.5 Q56.6 Q58.4 R91.2 ZD35.K(C)
SIG149: Q36.3 R59.1 R60.1 ZD22.A
SIG150: Q34.6 R58.2
SIG155: Q33.3 R55.1 R56.1 ZD20.A
SIG156: Q34.3 R56.2
SIG160: Q57.3 R90.2
SIG163: Q47.6 R77.2
SIG165: Q44.6 R73.2
SIG167: LED29.C LED30.A Q49.1 Q49.2 Q49.5 Q49.6 Q51.4 R80.2 ZD31.K(C)
SIG169: Q48.3 R76.1 R77.1 ZD29.A
SIG170: Q46.3 R74.1 R75.1 ZD28.A
SIG219: Q41.3 R65.1 R66.1 ZD25.A
SIG220: CON6.1 LED30.C Q51.1 Q51.2 Q51.5 Q51.6
SIG221: Q51.3 R80.1 R81.1 ZD31.A
SIG222: Q49.3 R78.1 R79.1 ZD30.A
SIG223: Q45.3 R72.1 R73.1 ZD27.A
SIG224: CON7.1 LED36.C Q61.1 Q61.2 Q61.5 Q61.6
SIG225: Q56.3 R89.1 R90.1 ZD34.A
SIG226: Q55.3 R87.1 R88.1 ZD33.A
SIG227: LED32.C LED33.A Q55.1 Q55.2 Q55.5 Q55.6 Q56.4 R89.2 ZD34.K(C)
SIG228: LED31.C LED32.A Q53.1 Q53.2 Q53.5 Q53.6 Q55.4 R87.2 ZD33.K(C)

Not connected (* = marked no-connect by the designer): LED19 P_3(NC); LED20 P_3(NC); LED21 P_3(NC); LED22 P_3(NC); LED23 P_3(NC); LED24 P_3(NC); LED25 P_3(NC); LED26 P_3(NC); LED27 P_3(NC); LED28 P_3(NC); LED29 P_3(NC); LED30 P_3(NC); LED31 P_3(NC); LED32 P_3(NC); LED33 P_3(NC); LED34 P_3(NC); LED35 P_3(NC); LED36 P_3(NC)

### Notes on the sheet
- 1608
- (near R56) 1608
- (near R71) 1608
- (near R86) 1608
- (near R58) 1608
- (near R73) 1608
- (near R88) 1608
- (near R60) 1608
- (near R75) 1608
- (near R90) 1608
- (near R62) 1608
- (near R77) 1608
- (near R92) 1608
- (near R64) 1608
- (near R79) 1608
- (near R94) 1608
- (near R66) 1608
- (near R81) 1608
- (near R96) 1608

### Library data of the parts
CON5-CON7 = C2A: as CON2 on sheet 1
LED19-LED36 = LEDC: as LED1 on sheet 1
Q33 Q35 Q36 Q38 Q39 Q41 Q43 Q45 Q46 Q48 Q49 Q51 Q53 Q55 Q56 Q58 Q59 Q61 = MFPF: as Q3 on sheet 1
Q34 Q37 Q40 Q44 Q47 Q50 Q54 Q57 Q60 = RN1907FE_1: as Q4 on sheet 1
R55 R64 R70 R79 R85 R94 = R: as R10 on sheet 1
R56 R63 R71 R78 R86 R93 = R: as R11 on sheet 1
R57 R72 R87 = R: as R12 on sheet 1
R58 R60 R73 R75 R88 R90 = R: as R13 on sheet 1
R59 R62 R74 R77 R89 R92 = R: as R14 on sheet 1
R61 R76 R91 = R: as R16 on sheet 1
R65 R80 R95 = R: as R20 on sheet 1
R66 R81 R96 = R: as R21 on sheet 1
U?#2 = WAKU_DEF100: as U?#1 on sheet 1
ZD20-ZD37 = ZD: as ZD2 on sheet 1

## Sheet 3.SchDoc
size 420 x 297 mm
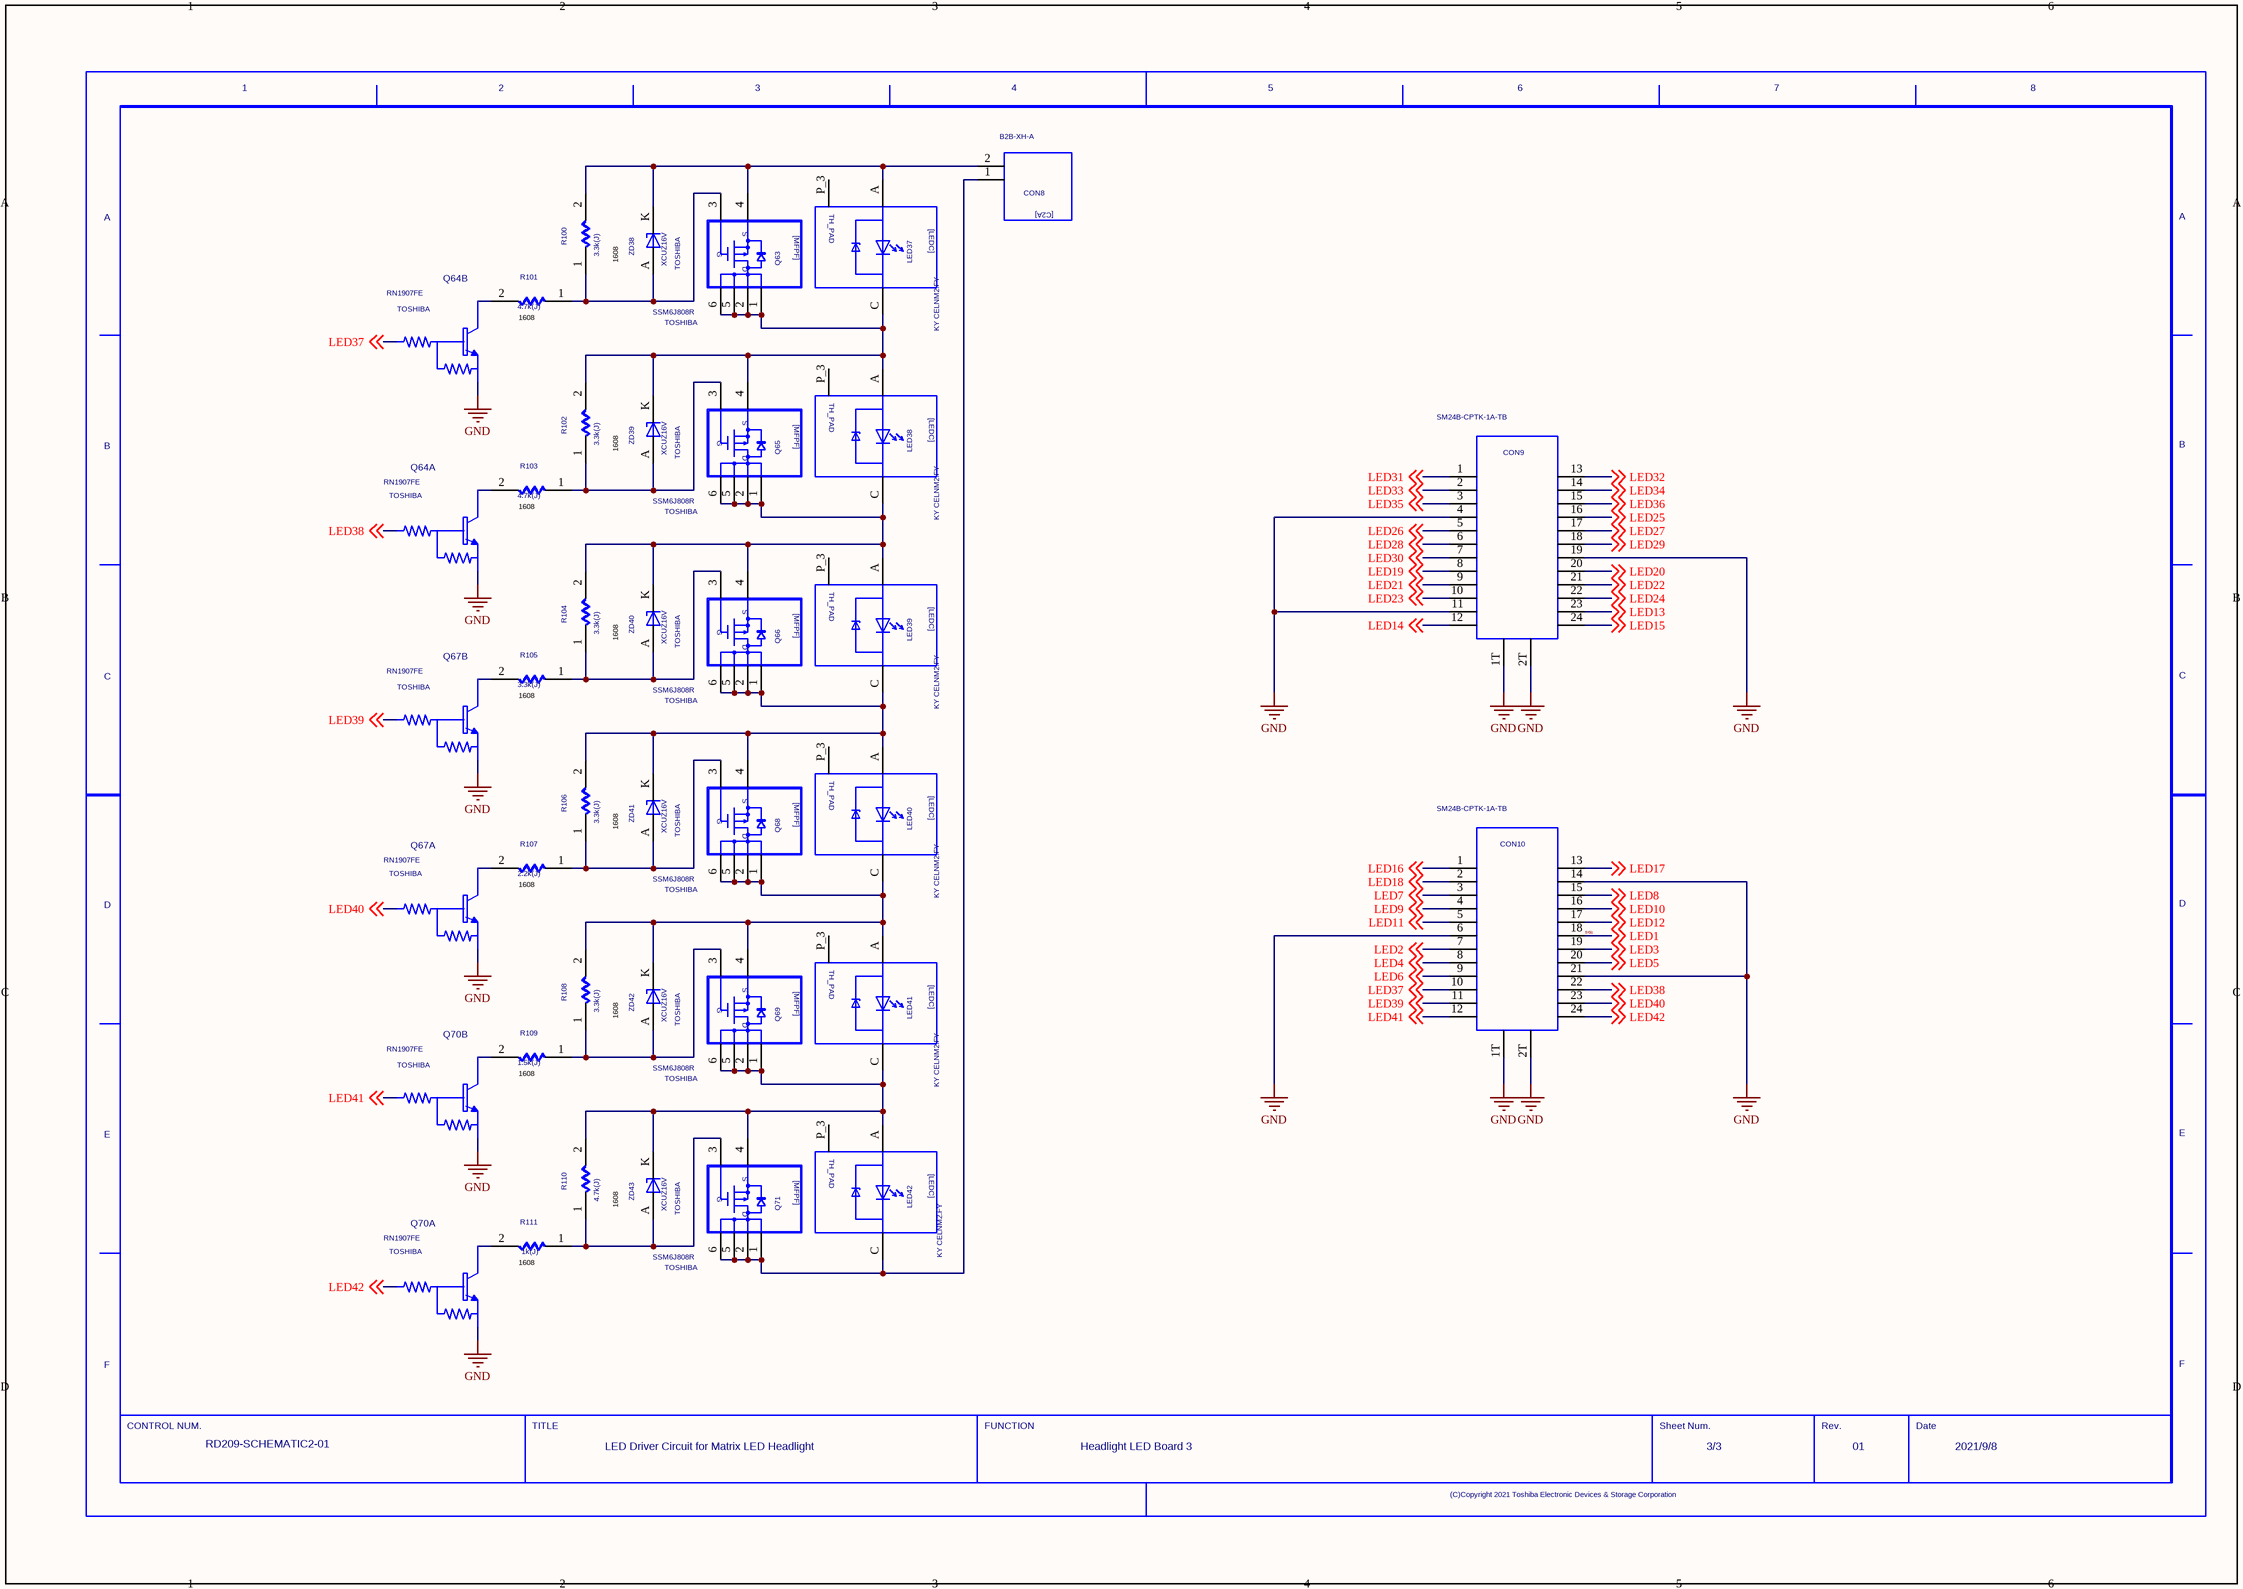
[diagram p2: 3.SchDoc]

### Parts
(Parts that share a designator on the sheet are numbered #1, #2 ... from top to bottom, then left to right.)
CON8  VAL3: B2B-XH-A  (hidden comment: C2A)
CON9  VAL3: SM24B-CPTK-1A-TB  (hidden comment: SM24B_CPTK_1A_TB)
CON10  VAL3: SM24B-CPTK-1A-TB  (hidden comment: SM24B_CPTK_1A_TB)
LED37  VAL3: KY CELNM2.FY  (hidden comment: LEDC)
LED38  VAL3: KY CELNM2.FY  (hidden comment: LEDC)
LED39  VAL3: KY CELNM2.FY  (hidden comment: LEDC)
LED40  VAL3: KY CELNM2.FY  (hidden comment: LEDC)
LED41  VAL3: KY CELNM2.FY  (hidden comment: LEDC)
LED42  VAL3: KY CELNM2.FY  (hidden comment: LEDC)
Q63  USERCOMPTEXT3: TOSHIBA  VAL3: SSM6J808R  (hidden comment: MFPF)
Q64  USERCOMPTEXT3: TOSHIBA  VAL3: RN1907FE  (hidden comment: RN1907FE_1)  (parts A,B of 2)
Q65  USERCOMPTEXT3: TOSHIBA  VAL3: SSM6J808R  (hidden comment: MFPF)
Q66  USERCOMPTEXT3: TOSHIBA  VAL3: SSM6J808R  (hidden comment: MFPF)
Q67  USERCOMPTEXT3: TOSHIBA  VAL3: RN1907FE  (hidden comment: RN1907FE_1)  (parts A,B of 2)
Q68  USERCOMPTEXT3: TOSHIBA  VAL3: SSM6J808R  (hidden comment: MFPF)
Q69  USERCOMPTEXT3: TOSHIBA  VAL3: SSM6J808R  (hidden comment: MFPF)
Q70  USERCOMPTEXT3: TOSHIBA  VAL3: RN1907FE  (hidden comment: RN1907FE_1)  (parts A,B of 2)
Q71  USERCOMPTEXT3: TOSHIBA  VAL3: SSM6J808R  (hidden comment: MFPF)
R100  VAL1: 3.3k(J)  (hidden comment: R)
R101  VAL1: 4.7k(J)  (hidden comment: R)
R102  VAL1: 3.3k(J)  (hidden comment: R)
R103  VAL1: 4.7k(J)  (hidden comment: R)
R104  VAL1: 3.3k(J)  (hidden comment: R)
R105  VAL1: 3.3k(J)  (hidden comment: R)
R106  VAL1: 3.3k(J)  (hidden comment: R)
R107  VAL1: 2.2k(J)  (hidden comment: R)
R108  VAL1: 3.3k(J)  (hidden comment: R)
R109  VAL1: 1.5k(J)  (hidden comment: R)
R110  VAL1: 4.7k(J)  (hidden comment: R)
R111  VAL1: 1k(J)  (hidden comment: R)
U?#3  DATE: 2021/9/8  REVISION: 01  SHEETNUMBER: 3/3  FUNCTION: Headlight LED Board 3  TITLE: LED Driver Circuit for / Matrix LED Headlight  DRAWINGNUMBER: RD209-SCHEMATIC2-01  (hidden comment: WAKU_DEF100)
ZD38  USERCOMPTEXT3: TOSHIBA  VAL3: XCUZ16V  (hidden comment: ZD)
ZD39  USERCOMPTEXT3: TOSHIBA  VAL3: XCUZ16V  (hidden comment: ZD)
ZD40  USERCOMPTEXT3: TOSHIBA  VAL3: XCUZ16V  (hidden comment: ZD)
ZD41  USERCOMPTEXT3: TOSHIBA  VAL3: XCUZ16V  (hidden comment: ZD)
ZD42  USERCOMPTEXT3: TOSHIBA  VAL3: XCUZ16V  (hidden comment: ZD)
ZD43  USERCOMPTEXT3: TOSHIBA  VAL3: XCUZ16V  (hidden comment: ZD)

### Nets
GND: CON9.1T CON9.2T CON9.4 CON9.11 CON9.19 CON10.1T CON10.2T CON10.6 CON10.14 CON10.21 Q64.1 Q64.4 Q67.1 Q67.4 Q70.1 Q70.4  [also labelled SIG174, SIG179, SIG182, SIG189, SIG195, SIG202, SIG203, SIG204, SIG205, SIG209, SIG210, SIG212, SIG213]  [project net SIG101]
LED2: CON10.7 ; off-sheet LED2
LED3: CON10.19 ; off-sheet LED3
LED4: CON10.8 ; off-sheet LED4
LED5: CON10.20 ; off-sheet LED5
LED6: CON10.9 ; off-sheet LED6
LED7: CON10.3 ; off-sheet LED7
LED8: CON10.15 ; off-sheet LED8
LED9: CON10.4 ; off-sheet LED9
LED10: CON10.16 ; off-sheet LED10
LED11: CON10.5 ; off-sheet LED11
LED12: CON10.17 ; off-sheet LED12
LED13: CON9.23 ; off-sheet LED13
LED14: CON9.12 ; off-sheet LED14
LED15: CON9.24 ; off-sheet LED15
LED16: CON10.1 ; off-sheet LED16
LED17: CON10.13 ; off-sheet LED17
LED18: CON10.2 ; off-sheet LED18
LED19: CON9.8 ; off-sheet LED19
LED20: CON9.20 ; off-sheet LED20
LED21: CON9.9 ; off-sheet LED21
LED22: CON9.21 ; off-sheet LED22
LED23: CON9.10 ; off-sheet LED23
LED24: CON9.22 ; off-sheet LED24
LED25: CON9.16 ; off-sheet LED25
LED26: CON9.5 ; off-sheet LED26
LED27: CON9.17 ; off-sheet LED27
LED28: CON9.6 ; off-sheet LED28
LED29: CON9.18 ; off-sheet LED29
LED30: CON9.7 ; off-sheet LED30
LED31: CON9.1 ; off-sheet LED31
LED32: CON9.13 ; off-sheet LED32
LED33: CON9.2 ; off-sheet LED33
LED34: CON9.14 ; off-sheet LED34
LED35: CON9.3 ; off-sheet LED35
LED36: CON9.15 ; off-sheet LED36
LED37: CON10.10 Q64.5 ; off-sheet LED37
LED38: CON10.22 Q64.2 ; off-sheet LED38
LED39: CON10.11 Q67.5 ; off-sheet LED39
LED40: CON10.23 Q67.2 ; off-sheet LED40
LED41: CON10.12 Q70.5 ; off-sheet LED41
LED42: CON10.24 Q70.2 ; off-sheet LED42
LED+7: CON8.2 LED37.A Q63.4 R100.2 ZD38.K(C)
SIG1: CON10.18 ; off-sheet LED1  [also labelled LED1]
SIG172: Q68.3 R106.1 R107.1 ZD41.A
SIG175: LED40.C LED41.A Q68.1 Q68.2 Q68.5 Q68.6 Q69.4 R108.2 ZD42.K(C)
SIG176: Q65.3 R102.1 R103.1 ZD39.A
SIG177: Q67.6 R107.2
SIG180: Q67.3 R105.2
SIG181: Q70.6 R111.2
SIG183: Q70.3 R109.2
SIG187: Q71.3 R110.1 R111.1 ZD43.A
SIG191: LED37.C LED38.A Q63.1 Q63.2 Q63.5 Q63.6 Q65.4 R102.2 ZD39.K(C)
SIG192: LED38.C LED39.A Q65.1 Q65.2 Q65.5 Q65.6 Q66.4 R104.2 ZD40.K(C)
SIG194: LED41.C LED42.A Q69.1 Q69.2 Q69.5 Q69.6 Q71.4 R110.2 ZD43.K(C)
SIG197: Q64.3 R101.2
SIG198: Q63.3 R100.1 R101.1 ZD38.A
SIG199: Q64.6 R103.2
SIG229: Q66.3 R104.1 R105.1 ZD40.A
SIG230: LED39.C LED40.A Q66.1 Q66.2 Q66.5 Q66.6 Q68.4 R106.2 ZD41.K(C)
SIG231: Q69.3 R108.1 R109.1 ZD42.A
SIG232: CON8.1 LED42.C Q71.1 Q71.2 Q71.5 Q71.6

Not connected (* = marked no-connect by the designer): LED37 P_3(NC); LED38 P_3(NC); LED39 P_3(NC); LED40 P_3(NC); LED41 P_3(NC); LED42 P_3(NC)

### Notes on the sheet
- 1608
- (near R101) 1608
- (near R103) 1608
- (near R105) 1608
- (near R107) 1608
- (near R109) 1608
- (near R111) 1608

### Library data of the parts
CON8 = C2A: as CON2 on sheet 1
CON9 CON10 = SM24B_CPTK_1A_TB: TIME: 12:18:04; UPDATEUSER: t5459927; UPDATETIME: 10:12:38; SAVECOUNT: 3; SAVEAREA0: -83685,-38329,109566,68648; OriginalSymbolOrigin: (5080,43180); COMPONENTNAME: GAS220000030
LED37-LED42 = LEDC: as LED1 on sheet 1
Q63 Q65 Q66 Q68 Q69 Q71 = MFPF: as Q3 on sheet 1
Q64 Q67 Q70 = RN1907FE_1: as Q4 on sheet 1
R100 R109 = R: as R10 on sheet 1
R101 R108 = R: as R11 on sheet 1
R102 = R: as R12 on sheet 1
R103 R105 = R: as R13 on sheet 1
R104 R107 = R: as R14 on sheet 1
R106 = R: as R16 on sheet 1
R110 = R: as R20 on sheet 1
R111 = R: as R21 on sheet 1
U?#3 = WAKU_DEF100: PLOTTIME: HH:MM; SAVEAREA0: 148187,-66180,486823,89919; TIME: 14:30:25; UPDATEUSER: t5459927; UPDATETIME: 14:28:23; SAVECOUNT: 6; OriginalSymbolOrigin: (10160,284480)
ZD38-ZD43 = ZD: as ZD2 on sheet 1

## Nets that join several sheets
SIG101: 1 (18 pins), 2 (18 pins), 3 (16 pins)
LED2: 1 (Q4.2), 3 (CON10.7)
LED3: 1 (Q7.5), 3 (CON10.19)
LED4: 1 (Q7.2), 3 (CON10.8)
LED5: 1 (Q10.5), 3 (CON10.20)
LED6: 1 (Q10.2), 3 (CON10.9)
LED7: 1 (Q14.5), 3 (CON10.3)
LED8: 1 (Q14.2), 3 (CON10.15)
LED9: 1 (Q17.5), 3 (CON10.4)
LED10: 1 (Q17.2), 3 (CON10.16)
LED11: 1 (Q20.5), 3 (CON10.5)
LED12: 1 (Q20.2), 3 (CON10.17)
LED13: 1 (Q24.5), 3 (CON9.23)
LED14: 1 (Q24.2), 3 (CON9.12)
LED15: 1 (Q27.5), 3 (CON9.24)
LED16: 1 (Q27.2), 3 (CON10.1)
LED17: 1 (Q30.5), 3 (CON10.13)
LED18: 1 (Q30.2), 3 (CON10.2)
LED19: 2 (Q34.5), 3 (CON9.8)
LED20: 2 (Q34.2), 3 (CON9.20)
LED21: 2 (Q37.5), 3 (CON9.9)
LED22: 2 (Q37.2), 3 (CON9.21)
LED23: 2 (Q40.5), 3 (CON9.10)
LED24: 2 (Q40.2), 3 (CON9.22)
LED25: 2 (Q44.5), 3 (CON9.16)
LED26: 2 (Q44.2), 3 (CON9.5)
LED27: 2 (Q47.5), 3 (CON9.17)
LED28: 2 (Q47.2), 3 (CON9.6)
LED29: 2 (Q50.5), 3 (CON9.18)
LED30: 2 (Q50.2), 3 (CON9.7)
LED31: 2 (Q54.5), 3 (CON9.1)
LED32: 2 (Q54.2), 3 (CON9.13)
LED33: 2 (Q57.5), 3 (CON9.2)
LED34: 2 (Q57.2), 3 (CON9.14)
LED35: 2 (Q60.5), 3 (CON9.3)
LED36: 2 (Q60.2), 3 (CON9.15)
SIG1: 1 (Q4.5), 3 (CON10.18)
